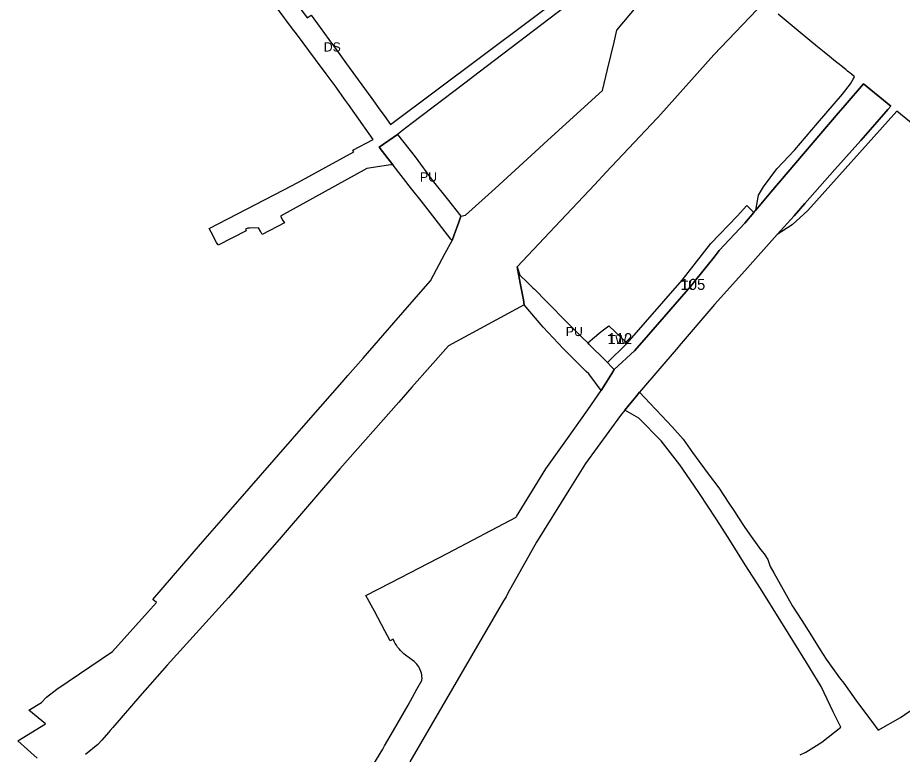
# Model space of a CAD drawing. Extents: x -537034 to -534353, y -1176562 to -1173176.
# Drawn here: x -536271.5 to -535789.3, y -1175263.6 to -1174862.1 of the extents above; entities that cross this region are included whole.
import ezdxf

# ---------------------------------------------------------------- set-up
doc = ezdxf.new("R2010")
doc.units = 0
for name, color, linetype in [('90320013', 7, 'Continuous'), ('90320023', 7, 'Continuous'), ('90330013', 7, 'Continuous'), ('90380023', 7, 'Continuous'), ('90390023', 7, 'Continuous'), ('90450013', 7, 'Continuous'), ('ID_navrh', 7, 'Continuous')]:
    doc.layers.add(name, color=color, linetype=linetype)

msp = doc.modelspace()

# ---------------------------------------------------------------- linework, layer by layer
at = {"layer": '90320013'}
for points in [[(-536123.18, -1174849.17), (-536113.67, -1174862.22), (-536111.47, -1174860.69), (-536106.55, -1174867.48), (-536101.82, -1174874.01), (-536096.81, -1174880.92), (-536092.2, -1174887.28), (-536082.49, -1174900.65), (-536078.52, -1174906.12), (-536073.49, -1174913.05), (-536071.8, -1174915.38), (-536068.27, -1174920.24), (-535917.53, -1174807.16)], [(-535913.69, -1174810.62), (-536019.96, -1174891.69), (-536027.83, -1174897.7), (-536056.94, -1174919.98), (-536061.63, -1174923.56), (-536064.36, -1174925.66), (-536074.52, -1174932.56), (-536069.45, -1174939.06), (-536066.78, -1174942.48), (-536068.21, -1174942.34), (-536081.08, -1174944.24), (-536128.29, -1174970.2), (-536126.86, -1174972.63), (-536126.13, -1174973.87), (-536138.15, -1174980.33), (-536138.99, -1174978.78), (-536140.21, -1174976.54), (-536145.01, -1174976.76), (-536146.01, -1174976.8), (-536147.32, -1174977.4), (-536147, -1174978.2), (-536162.24, -1174986.05), (-536162.42, -1174985.71), (-536163.02, -1174984.62), (-536164.66, -1174981.59), (-536164.96, -1174981.04), (-536167.15, -1174977.02), (-536126.39, -1174955.85), (-536118.72, -1174951.96), (-536088.24, -1174935.26), (-536088.82, -1174934.21), (-536077.76, -1174928.41), (-536087.7, -1174914.34), (-536091.18, -1174909.41), (-536093.29, -1174906.43), (-536097.82, -1174900.02), (-536103.25, -1174892.72), (-536109.09, -1174884.87), (-536119.51, -1174870.86), (-536121.6, -1174868.06), (-536129.48, -1174857.58)], [(-536079.94, -1175273.05), (-536072.44, -1175260.84), (-536071.45, -1175259.11), (-536066.56, -1175250.59), (-536058.69, -1175236.86), (-536053.84, -1175228.22), (-536051.13, -1175223.39), (-536051.08, -1175222.17), (-536051.12, -1175221.23), (-536051.24, -1175220.3), (-536051.43, -1175219.38), (-536051.69, -1175218.48), (-536052.02, -1175217.6), (-536052.42, -1175216.75), (-536052.88, -1175215.93), (-536053.41, -1175215.15), (-536053.99, -1175214.42), (-536054.64, -1175213.73), (-536055.33, -1175213.1), (-536056.07, -1175212.52), (-536060.06, -1175209.57), (-536061.02, -1175208.81), (-536061.93, -1175207.99), (-536062.79, -1175207.11), (-536063.6, -1175206.19), (-536064.36, -1175205.22), (-536065.05, -1175204.21), (-536065.69, -1175203.16), (-536066.26, -1175202.08), (-536066.77, -1175200.96), (-536068.42, -1175201.8), (-536071.39, -1175196.25), (-536077.03, -1175185.69), (-536081.63, -1175177.09), (-536068.2, -1175170.14), (-536037.06, -1175154.03), (-535999.76, -1175134.32), (-535999.49, -1175133.94), (-535983.6, -1175108.09), (-535971.74, -1175091.4), (-535960.73, -1175075.89), (-535953.43, -1175065.31), (-535951.27, -1175061.84), (-535947.68, -1175056.08), (-535946.27, -1175053.83), (-535935.2, -1175043.72), (-535931.23, -1175039.16), (-535915.41, -1175020.97), (-535904.71, -1175008.67), (-535901.77, -1175004.97), (-535891.9, -1174992.57), (-535889.1, -1174989.05), (-535875.03, -1174974.16), (-535870.12, -1174968.27), (-535869.09, -1174967.04), (-535860.85, -1174957.16), (-535824.3, -1174914.18), (-535820.47, -1174909.67), (-535810.49, -1174898.11), (-535795.61, -1174910.22), (-535797.25, -1174912.13), (-535798.3, -1174913.34), (-535804.23, -1174920.24), (-535811.96, -1174928.98), (-535826.02, -1174944.87), (-535842.32, -1174963.3), (-535848.23, -1174969.99), (-535857.44, -1174980.33), (-535875.11, -1175000.15), (-535891.57, -1175018.42), (-535892.58, -1175019.54), (-535910.84, -1175040.91), (-535911.5, -1175041.69), (-535932.5, -1175066.27), (-535934.49, -1175068.7), (-535938.1, -1175073.13), (-535940.45, -1175076), (-535942.92, -1175078.93), (-535962.02, -1175105.09), (-535971.05, -1175119.6), (-535988.63, -1175148), (-536004.23, -1175175.83), (-536005.29, -1175177.79), (-536006.58, -1175180), (-536057.72, -1175267.69)]]:
    msp.add_lwpolyline(points, dxfattribs=at)
at = {"layer": '90320023'}
msp.add_lwpolyline([(-535763.77, -1174936.3), (-535792.27, -1174912.94), (-535840.8, -1174967.19), (-535849.28, -1174975.01), (-535857.44, -1174980.33), (-535848.23, -1174969.99), (-535842.32, -1174963.3), (-535826.02, -1174944.87), (-535811.96, -1174928.98), (-535804.23, -1174920.24), (-535798.3, -1174913.34), (-535797.25, -1174912.13), (-535795.61, -1174910.22), (-535810.49, -1174898.11), (-535820.47, -1174909.67), (-535824.3, -1174914.18), (-535860.85, -1174957.16), (-535869.09, -1174967.04), (-535867.71, -1174958.89), (-535864.89, -1174954.2), (-535857.7, -1174944.51), (-535847.89, -1174934.15), (-535835.42, -1174919.52), (-535821.9, -1174903.73), (-535817.52, -1174898.06), (-535816.08, -1174895.56), (-535815.76, -1174895.01), (-535815.31, -1174894.19), (-535815.51, -1174894.03), (-535816.96, -1174892.85), (-535817.85, -1174892.16), (-535818.12, -1174891.95), (-535818.47, -1174891.67), (-535819.13, -1174891.14), (-535820.1, -1174890.37), (-535822.62, -1174888.35), (-535823.53, -1174887.61), (-535825.72, -1174885.85), (-535828.91, -1174883.28), (-535832.7, -1174880.19), (-535835.45, -1174877.94), (-535839.59, -1174874.57), (-535847.18, -1174868.32), (-535856.91, -1174860.12)], dxfattribs=at)
at = {"layer": '90330013'}
for points in [[(-536260.91, -1175265.77), (-536271.48, -1175256.23), (-536256.34, -1175246.96), (-536265.43, -1175239.57), (-536258.52, -1175235.47), (-536255.83, -1175232.42), (-536250.18, -1175228.11), (-536219.8, -1175207.64), (-536200.72, -1175186.28), (-536195.87, -1175180.85), (-536197.75, -1175179.34), (-536171.85, -1175149.13), (-536169.31, -1175146.17), (-536157.93, -1175133.14), (-536145.36, -1175118.77), (-536131.68, -1175103.11), (-536111.69, -1175080.24), (-536094.69, -1175060.78), (-536091.51, -1175057.14), (-536083.18, -1175047.59), (-536066.52, -1175028.5), (-536050.45, -1175010.1), (-536046.43, -1175005.49), (-536038.38, -1174990.43), (-536034.72, -1174983.59), (-536033.55, -1174980.42), (-536031.04, -1174973.59), (-536029.84, -1174970.32), (-536027.29, -1174969.79), (-536011.27, -1174955.13), (-535989.44, -1174935.16), (-535982.41, -1174928.78), (-535952.7, -1174901.83), (-535949.95, -1174890.31), (-535946.34, -1174875.4), (-535944.85, -1174868.93), (-535910.56, -1174827.75)], [(-535864.6, -1174853.66), (-535892.04, -1174882.37), (-535920.96, -1174914.72), (-535922.59, -1174916.55), (-535923.09, -1174917.08), (-535950.62, -1174946.32), (-535957.11, -1174953.22), (-535981.6, -1174979.24), (-535999.15, -1174997.89), (-535997.52, -1175006.7), (-535995.81, -1175015.9), (-535995.32, -1175018.56), (-536036.63, -1175040.94), (-536056.68, -1175063.43), (-536063.63, -1175071.65), (-536095.85, -1175107.94), (-536127.83, -1175145.22), (-536156.5, -1175178.11), (-536189.92, -1175215.07), (-536204.88, -1175232.04), (-536219.68, -1175249.12), (-536221, -1175250.62), (-536221.99, -1175251.75), (-536225.62, -1175255.88), (-536227.77, -1175258.32), (-536234.54, -1175263.73)]]:
    msp.add_lwpolyline(points, dxfattribs=at)
at = {"layer": '90380023'}
msp.add_lwpolyline([(-535950.02, -1175050.07), (-535939.54, -1175039.81), (-535939.34, -1175039.57), (-535909.22, -1175005.11), (-535905.99, -1175000.94), (-535893.73, -1174985.12), (-535879.3, -1174970.34), (-535874.11, -1174964.42), (-535871.51, -1174966.94), (-535870.12, -1174968.27), (-535875.03, -1174974.16), (-535889.1, -1174989.05), (-535891.9, -1174992.57), (-535901.77, -1175004.97), (-535904.71, -1175008.67), (-535915.41, -1175020.97), (-535931.23, -1175039.16), (-535935.2, -1175043.72), (-535946.27, -1175053.83), (-535948.1, -1175051.99)], close=True, dxfattribs=at)
at = {"layer": '90390023'}
msp.add_lwpolyline([(-535950.02, -1175050.07), (-535951.25, -1175048.83), (-535954.03, -1175046.03), (-535957.18, -1175042.87), (-535960.06, -1175039.98), (-535960.76, -1175039.28), (-535958.18, -1175037.19), (-535953.57, -1175033.41), (-535949.3, -1175029.98), (-535939.34, -1175039.57), (-535939.54, -1175039.81)], close=True, dxfattribs=at)
at = {"layer": '90450013'}
for points in [[(-536064.36, -1174925.66), (-536054.81, -1174937.9), (-536045.57, -1174950.72), (-536037.44, -1174960.85), (-536029.84, -1174970.32), (-536031.04, -1174973.59), (-536033.55, -1174980.42), (-536034.72, -1174983.59), (-536035.38, -1174982.75), (-536045.18, -1174970.17), (-536051.59, -1174961.96), (-536056.76, -1174955.33), (-536066.78, -1174942.48), (-536069.45, -1174939.06), (-536074.52, -1174932.56)], [(-535950.02, -1175050.07), (-535948.1, -1175051.99), (-535946.27, -1175053.83), (-535947.68, -1175056.08), (-535951.27, -1175061.84), (-535953.43, -1175065.31), (-535960.11, -1175056.29), (-535961.54, -1175054.89), (-535974.14, -1175042.47), (-535985, -1175030.71), (-535995.32, -1175018.56), (-535995.81, -1175015.9), (-535997.52, -1175006.7), (-535999.15, -1174997.89), (-535997.81, -1175002.4), (-535993.82, -1175006.26), (-535990.61, -1175009.36), (-535989.83, -1175010.11), (-535983.28, -1175016.79), (-535971.69, -1175028.41), (-535963.89, -1175036.28), (-535960.76, -1175039.28), (-535960.06, -1175039.98), (-535957.18, -1175042.87), (-535954.03, -1175046.03), (-535951.25, -1175048.83)]]:
    msp.add_lwpolyline(points, close=True, dxfattribs=at)
msp.add_lwpolyline([(-535845.03, -1175263.95), (-535841.93, -1175262.54), (-535833.14, -1175257.04), (-535822.83, -1175248.77), (-535826.99, -1175240.54), (-535833.51, -1175226.59), (-535841.48, -1175213.52), (-535848.95, -1175201.61), (-535851.26, -1175197.86), (-535855.44, -1175191.03), (-535866.66, -1175173.32), (-535874.88, -1175160.36), (-535883.37, -1175146.98), (-535888.83, -1175138.4), (-535890.81, -1175135.33), (-535899.77, -1175121.47), (-535902.88, -1175116.95), (-535910.5, -1175105.81), (-535920.7, -1175092.83), (-535932.84, -1175080.34), (-535940.45, -1175076), (-535938.1, -1175073.13), (-535934.49, -1175068.7), (-535932.5, -1175066.27), (-535926.71, -1175072.4), (-535923.55, -1175075.74), (-535923.3, -1175076.01), (-535920.56, -1175078.91), (-535914.65, -1175085.2), (-535908.65, -1175091.8), (-535903.72, -1175099.08), (-535895.04, -1175110.69), (-535889.28, -1175118.4), (-535883.77, -1175126.82), (-535880.81, -1175131.35), (-535878.49, -1175134.79), (-535875.39, -1175139.39), (-535872.51, -1175143.66), (-535867.39, -1175150.75), (-535866.53, -1175151.94), (-535864.66, -1175154.36), (-535862.55, -1175157.44), (-535861.27, -1175161.21), (-535859.27, -1175164.64), (-535849.05, -1175182.83), (-535844.11, -1175190.68), (-535839.28, -1175198.1), (-535834.1, -1175206.69), (-535830.7, -1175211.83), (-535823.58, -1175221.99), (-535821.08, -1175224.95), (-535814.6, -1175234.05), (-535807.61, -1175243.4), (-535805.87, -1175245.73), (-535802.34, -1175250.49), (-535790.26, -1175243.55), (-535777.3, -1175234.67)], dxfattribs=at)

# ---------------------------------------------------------------- texts
at = {"layer": '90320013'}
msp.add_text('DS', height=5, rotation=0, dxfattribs=at).set_placement((-536104.63, -1174880.5))
at = {"layer": '90380023'}
msp.add_text('TU', height=5, rotation=360, dxfattribs=at).set_placement((-535910.07, -1175010.46))
at = {"layer": '90390023'}
msp.add_text('TW', height=5, rotation=360, dxfattribs=at).set_placement((-535949.89, -1175040.03))
at = {"layer": '90450013'}
for p in [(-536052.18, -1174951.38), (-535972.71, -1175035.63)]:
    msp.add_text('PU', height=5, rotation=0, dxfattribs=at).set_placement(p)
at = {"layer": 'ID_navrh'}
for s, p in [('105', (-535910.07, -1175010.46)), ('112', (-535949.89, -1175040.03))]:
    msp.add_text(s, height=6, rotation=360, dxfattribs=at).set_placement(p)

doc.saveas('drawing.dxf')
